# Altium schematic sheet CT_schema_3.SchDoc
size 321 x 309 mm
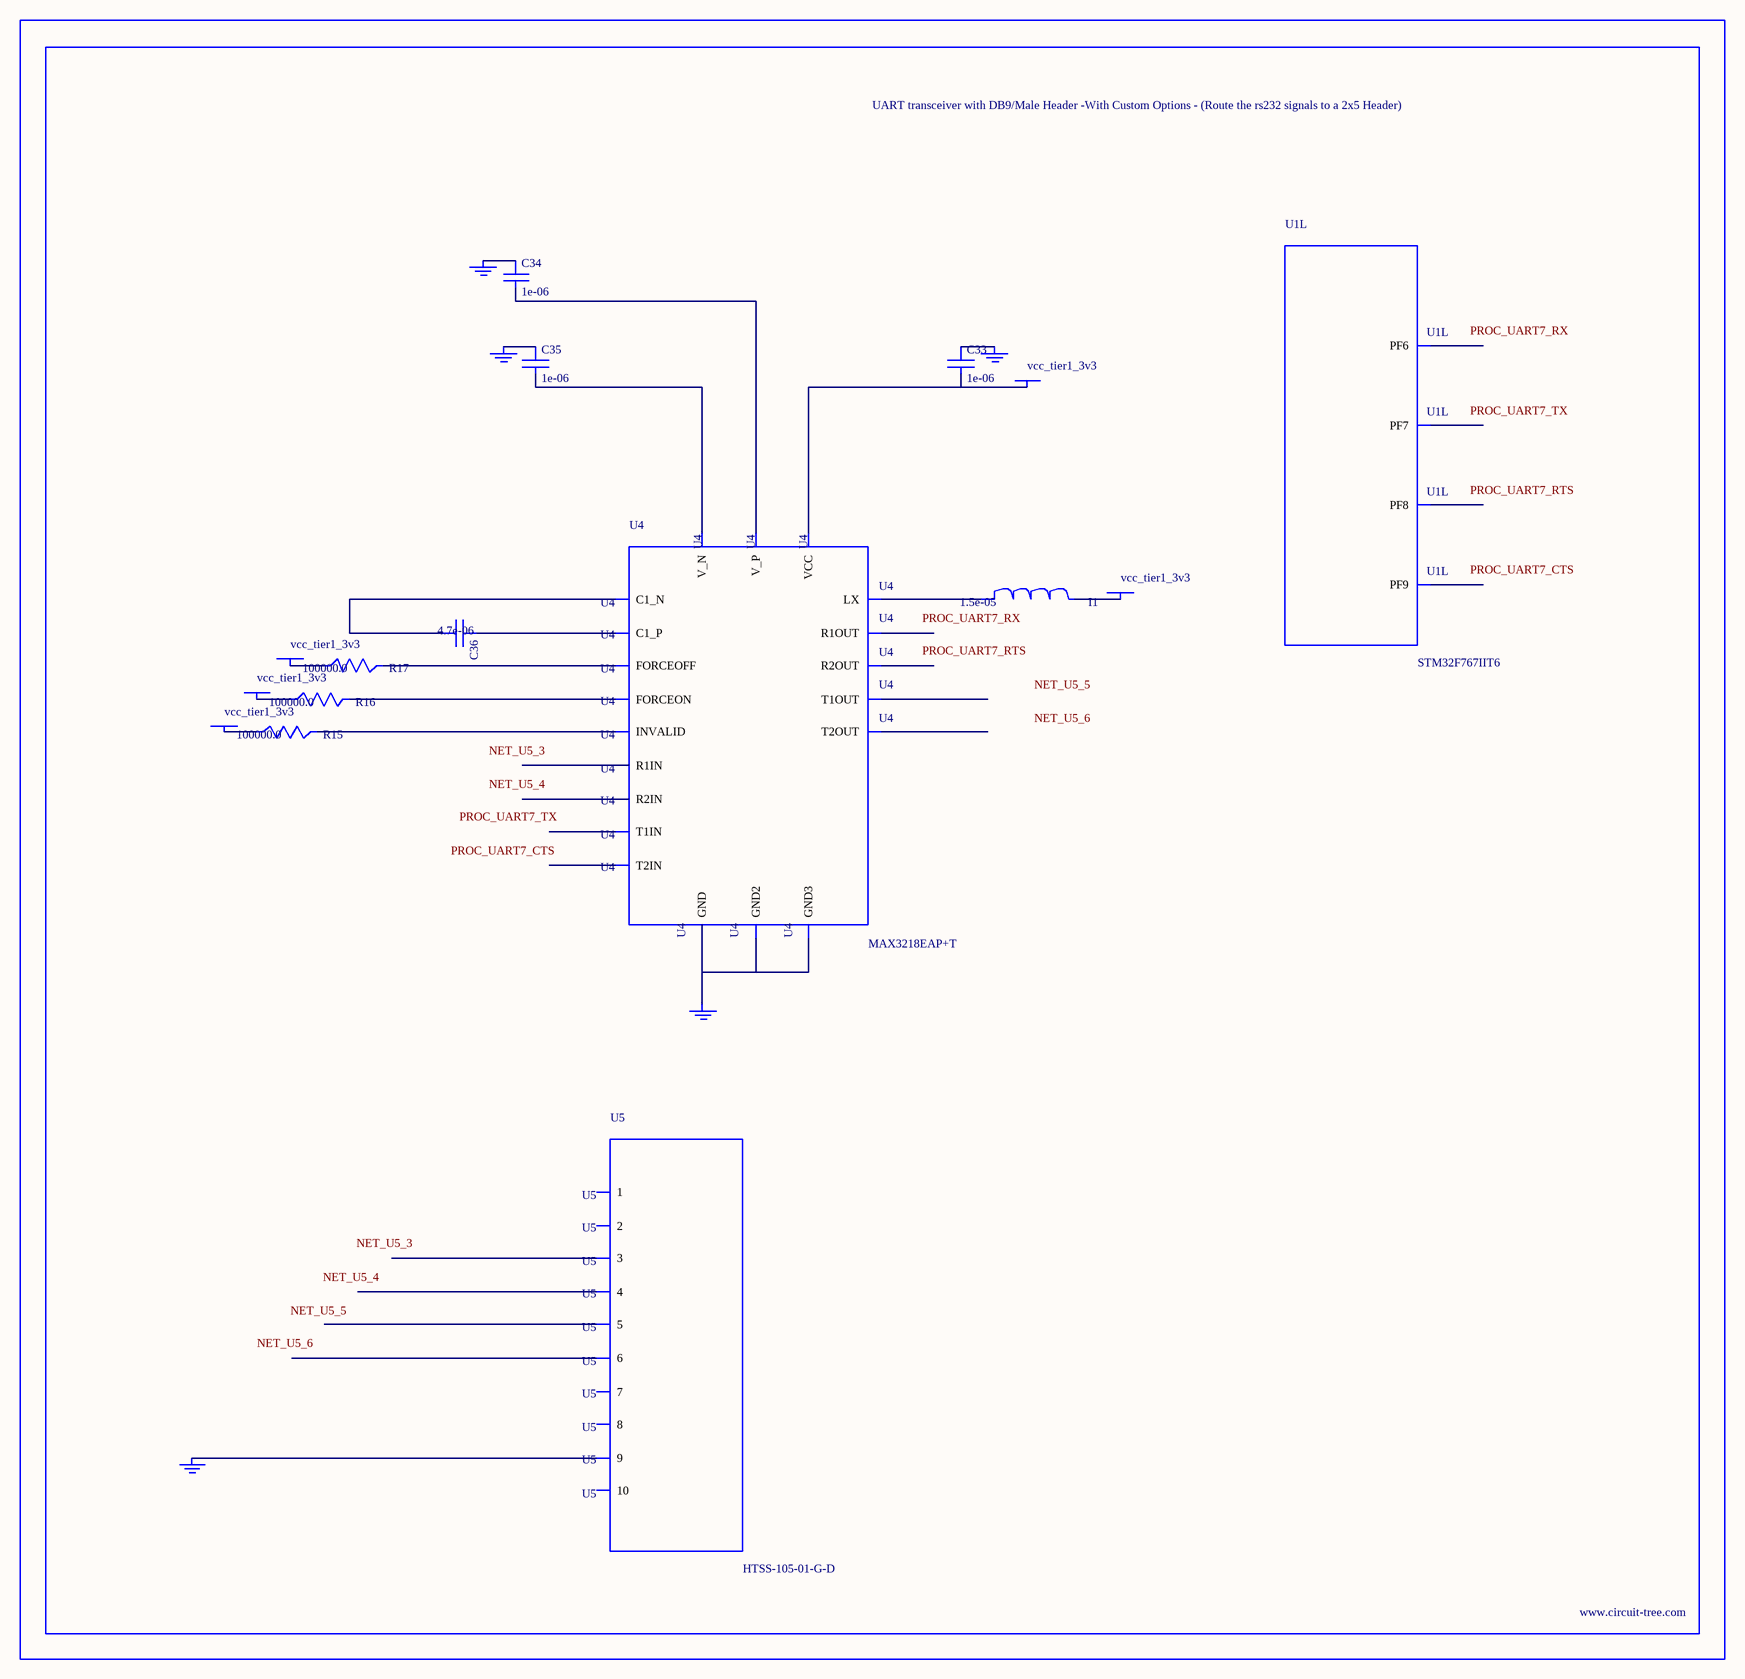
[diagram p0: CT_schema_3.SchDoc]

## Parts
BORDER2  (no value)
C33  1e-06  [C0603]
C34  1e-06  [C0603]
C35  1e-06  [C0603]
C36  4.7e-06  [C0805]
GND_INSTANCE_2_0  (no value)
GND_INSTANCE_2_1  (no value)
GND_INSTANCE_2_2  (no value)
GND_INSTANCE_2_3  (no value)
GND_INSTANCE_2_4  (no value)
I1  1.5e-05  [L1210]
POWER_INSTANCE_2_0  vcc_tier1_3v3
POWER_INSTANCE_2_1  vcc_tier1_3v3
POWER_INSTANCE_2_2  vcc_tier1_3v3
POWER_INSTANCE_2_3  vcc_tier1_3v3
POWER_INSTANCE_2_4  vcc_tier1_3v3
R15  100000.0  [R0603]
R16  100000.0  [R0603]
R17  100000.0  [R0603]
U1  STM32F767IIT6  [LQFP176]  (part L of 15)
U4  MAX3218EAP+T  [SSOP-20]
U5  HTSS-105-01-G-D  [HTSS-105-01-G-D]

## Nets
NetC33_1: C33.1 GND_INSTANCE_2_0.0(GND)
NetC33_2: C33.2 POWER_INSTANCE_2_4.0(PWR) U4.6(VCC)
NetC34_1: C34.1 GND_INSTANCE_2_2.0(GND)
NetC34_2: C34.2 U4.19(V_P)
NetC35_1: C35.1 GND_INSTANCE_2_1.0(GND)
NetC35_2: C35.2 U4.15(V_N)
NetC36_1: C36.1 U4.18(C1_P)
NetC36_2: C36.2 U4.16(C1_N)
NetGND_INSTANCE_2_3_0: GND_INSTANCE_2_3.0(GND) U4.5(GND) U4.17(GND2) U4.20(GND3)
NetGND_INSTANCE_2_4_0: GND_INSTANCE_2_4.0(GND) U5.9
NetI1_1: I1.1 U4.1(LX)
NetI1_2: I1.2 POWER_INSTANCE_2_0.0(PWR)
NetPOWER_INSTANCE_2_1_0: POWER_INSTANCE_2_1.0(PWR) R15.1
NetPOWER_INSTANCE_2_2_0: POWER_INSTANCE_2_2.0(PWR) R16.1
NetPOWER_INSTANCE_2_3_0: POWER_INSTANCE_2_3.0(PWR) R17.1
NetR15_2: R15.2 U4.2(INVALID)
NetR16_2: R16.2 U4.3(FORCEON)
NetR17_2: R17.2 U4.4(FORCEOFF)

Not connected (* = marked no-connect by the designer): U1 24(PF6) 25(PF7) 26(PF8) 27(PF9); U4 7(T1IN) 8(T2IN) 9(R1OUT) 10(R2OUT) 11(R2IN) 12(R1IN) 13(T2OUT) 14(T1OUT); U5 1 2 3 4 5 6 7 8 10

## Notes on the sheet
- Labels drawn without touching a wire or pin: NET_U5_3, NET_U5_4, NET_U5_5, NET_U5_6, PROC_UART7_CTS, PROC_UART7_RTS, PROC_UART7_RX, PROC_UART7_TX

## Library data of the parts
BORDER2 = BORDER_PAGE2
C33-C35 = C0603C105K3RACTU
C36 = C0805C475K4RACTU
GND_INSTANCE_2_0-GND_INSTANCE_2_4 = GND
I1 = L1210R150MDWIT
POWER_INSTANCE_2_0-POWER_INSTANCE_2_4 = PWR
R15-R17 = RC0603JR-07100KL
